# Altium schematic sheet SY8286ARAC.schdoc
size 127 x 101 mm
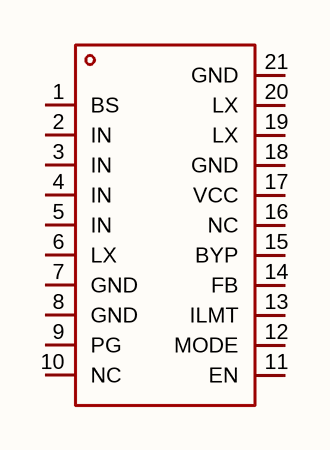
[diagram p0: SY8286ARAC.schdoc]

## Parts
U?  sy8286arac  [QFN-20_L3.0-W3.0-P0.45-BL-EP1.0]  (value not drawn)

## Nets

Not connected (* = marked no-connect by the designer): U? 1(BS) 2(IN) 3(IN) 4(IN) 5(IN) 6(LX) 7(GND) 8(GND) 9(PG) 10(NC) 11(EN) 12(MODE) 13(ILMT) 14(FB) 15(BYP) 16(NC) 17(VCC) 18(GND) 19(LX) 20(LX) 21(GND)

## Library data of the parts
U? = sy8286arac: 功能类型:降压型;工作电压:4V~23V;输出电压:-;输出电流:6A;输出类型:可调;; Manufacturer: Silergy(矽力杰); AddInBom: yes; ModelId: 993738199e794b9a9ab189fd78fc7651; ModelTransform: 118.8974,118.8974,0,90,0,0,0.007,-0.002,0; Function: 降压型; Voltage - Supply: 4V~23V; Output Current: 6A; Frequency - Switching: 510kHz~690kHz; Synchronous Rectifier: 是; Number of Outputs: 1; Topology: 降压式; Quiescent Current: 120uA; Switch tube (built-in/external): 内置; Output Type: 可调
